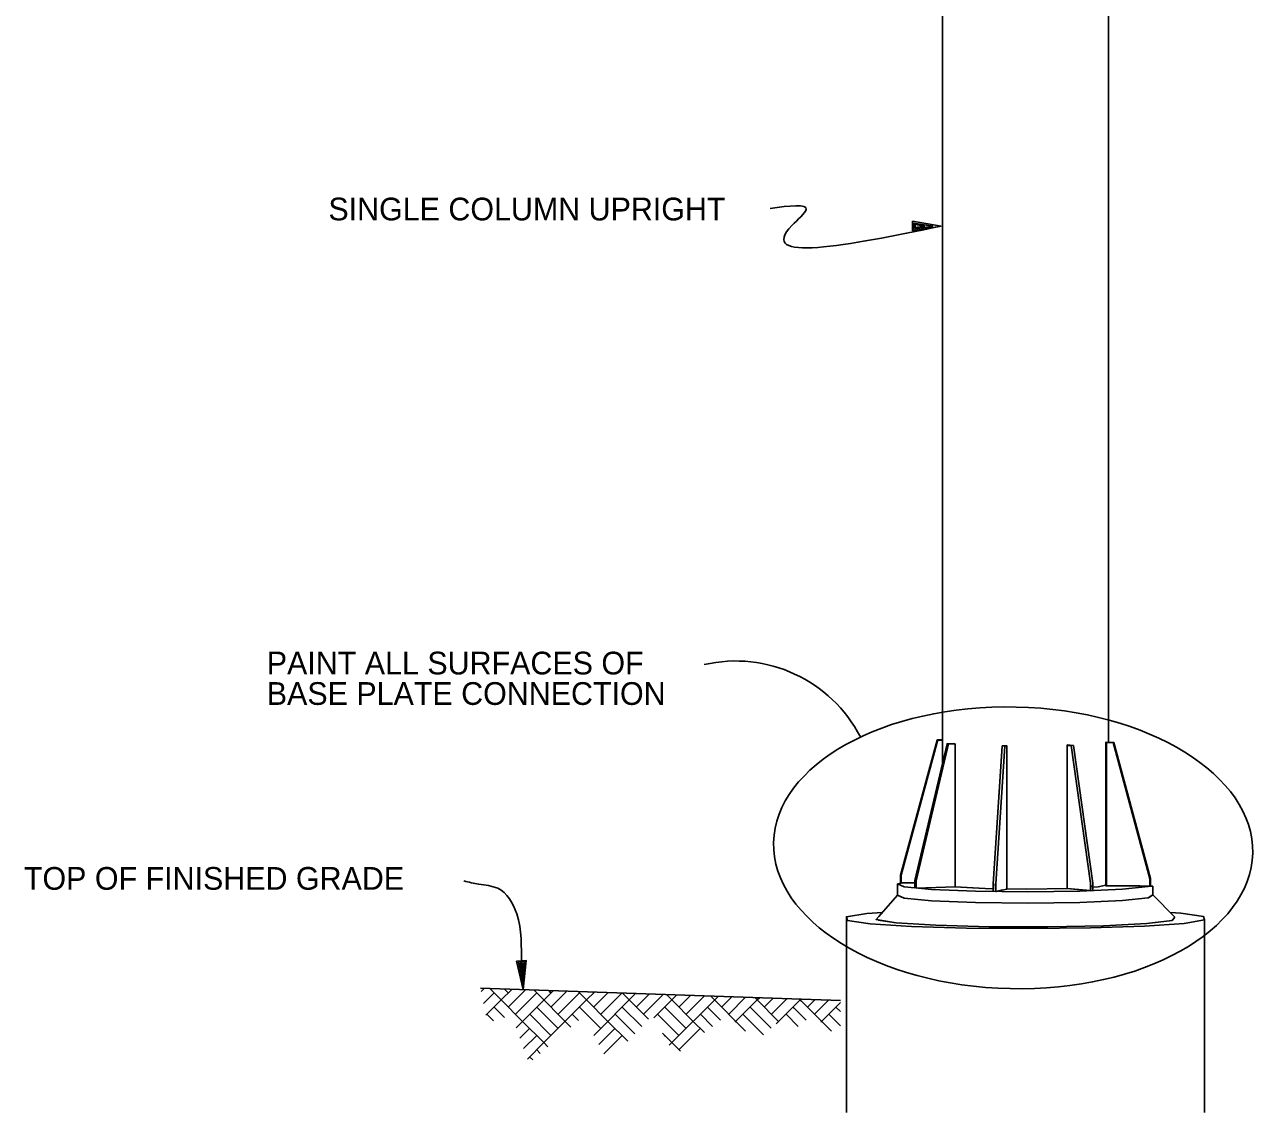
# Model space of a CAD drawing. Extents: x 10268852 to 10269008, y 2142584 to 2142686.
# Drawn here: x 10268878.83 to 10268915.61, y 2142620.73 to 2142653.26 of the extents above; entities that cross this region are included whole.
import ezdxf

# ---------------------------------------------------------------- set-up
doc = ezdxf.new("R2010")
doc.units = 0
doc.layers.add('SignDetail', color=7, linetype='Continuous')
doc.layers.add('TextLabel', color=7, linetype='Continuous')

msp = doc.modelspace()

# ---------------------------------------------------------------- linework, layer by layer
at = {"layer": 'SignDetail'}
for p, q in [((10268892.471, 2142624.439), (10268903.226, 2142624.073)), ((10268894.15, 2142624.302), (10268893.511, 2142623.664)), ((10268894.787, 2142623.666), (10268895.423, 2142624.302)), ((10268893.085, 2142624.09), (10268893.724, 2142623.451)), ((10268894.15, 2142623.877), (10268894.787, 2142623.24)), ((10268895, 2142623.453), (10268895.636, 2142624.09)), ((10268895.423, 2142623.877), (10268896.062, 2142623.238)), ((10268895.636, 2142624.09), (10268896.275, 2142623.451)), ((10268897.975, 2142623.877), (10268898.613, 2142623.238)), ((10268898.187, 2142624.09), (10268898.827, 2142623.451)), ((10268900.102, 2142623.453), (10268900.739, 2142624.09)), ((10268900.739, 2142624.09), (10268901.378, 2142623.451)), ((10268902.667, 2142623.453), (10268903.226, 2142624.012)), ((10268893.937, 2142623.664), (10268894.574, 2142623.027)), ((10268897.762, 2142623.664), (10268898.401, 2142623.025)), ((10268893.724, 2142623.451), (10268894.361, 2142622.814)), ((10268895, 2142623.453), (10268894.361, 2142622.814)), ((10268898.401, 2142622.603), (10268899.038, 2142623.24))]:
    msp.add_line(p, q, dxfattribs=at)
for points in [[(10268906.277, 2142665.654), (10268906.277, 2142631.914)], [(10268911.246, 2142663.913), (10268911.246, 2142631.798)], [(10268906.277, 2142647.077), (10268906.277, 2142631.161)], [(10268911.246, 2142647.077), (10268911.246, 2142631.797)], [(10268905.449, 2142627.589), (10268905.025, 2142627.595), (10268905.025, 2142627.82), (10268906.121, 2142631.864), (10268906.277, 2142631.862)], [(10268905.449, 2142627.589), (10268905.025, 2142627.595), (10268905.025, 2142627.82), (10268906.121, 2142631.864)], [(10268905.449, 2142627.593), (10268905.045, 2142627.599), (10268905.045, 2142627.825), (10268906.142, 2142631.869), (10268906.277, 2142631.867)], [(10268905.449, 2142627.593), (10268905.045, 2142627.599), (10268905.045, 2142627.825), (10268906.142, 2142631.869)], [(10268905.449, 2142627.435), (10268905.449, 2142627.66), (10268906.417, 2142631.753), (10268906.61, 2142631.759)], [(10268905.449, 2142627.66), (10268906.417, 2142631.753)], [(10268905.449, 2142627.66), (10268906.417, 2142631.753)], [(10268906.654, 2142631.755), (10268906.461, 2142631.748), (10268905.493, 2142627.656), (10268905.493, 2142627.43), (10268906.654, 2142627.47), (10268906.654, 2142631.755)], [(10268905.493, 2142627.656), (10268906.461, 2142631.748)], [(10268906.277, 2142631.862), (10268906.121, 2142631.864), (10268906.142, 2142631.869), (10268906.277, 2142631.867)], [(10268906.142, 2142631.869), (10268906.277, 2142631.867)], [(10268906.417, 2142631.753), (10268906.61, 2142631.759)], [(10268906.461, 2142631.748), (10268906.654, 2142631.755)], [(10268907.793, 2142627.56), (10268908.067, 2142631.695)], [(10268907.793, 2142627.56), (10268908.066, 2142631.681)], [(10268907.793, 2142627.335), (10268907.793, 2142627.56), (10268908.066, 2142631.681)], [(10268908.203, 2142627.408), (10268907.875, 2142627.334), (10268907.875, 2142627.559), (10268908.148, 2142631.68), (10268908.203, 2142631.692), (10268908.203, 2142627.408)], [(10268907.875, 2142627.559), (10268908.148, 2142631.68)], [(10268908.067, 2142631.695), (10268908.203, 2142631.692), (10268908.203, 2142627.408)], [(10268908.148, 2142631.68), (10268908.203, 2142631.692)], [(10268908.203, 2142631.693), (10268908.203, 2142627.408)], [(10268910.042, 2142631.704), (10268910.122, 2142631.697), (10268910.705, 2142627.583), (10268910.705, 2142627.358), (10268910.006, 2142627.423), (10268910.006, 2142631.717)], [(10268910.006, 2142631.717), (10268910.195, 2142631.699), (10268910.777, 2142627.585), (10268910.777, 2142627.36)], [(10268910.122, 2142631.697), (10268910.042, 2142631.704)], [(10268910.122, 2142631.697), (10268910.705, 2142627.583)], [(10268910.777, 2142627.585), (10268910.195, 2142631.7)], [(10268910.777, 2142627.585), (10268910.195, 2142631.699)], [(10268912.478, 2142627.715), (10268911.381, 2142631.79), (10268911.162, 2142631.793), (10268911.162, 2142627.508), (10268912.478, 2142627.49), (10268912.478, 2142627.715)], [(10268911.162, 2142631.793), (10268911.381, 2142631.79)], [(10268912.498, 2142627.495), (10268912.498, 2142627.72), (10268911.402, 2142631.795), (10268911.183, 2142631.798), (10268911.183, 2142627.513), (10268912.498, 2142627.495)], [(10268911.183, 2142631.798), (10268911.402, 2142631.795)], [(10268911.183, 2142631.798), (10268911.402, 2142631.795)], [(10268911.381, 2142631.79), (10268912.478, 2142627.715)], [(10268911.402, 2142631.795), (10268912.498, 2142627.72)], [(10268905.449, 2142627.444), (10268905.131, 2142627.474), (10268904.936, 2142627.563), (10268905.099, 2142627.593)], [(10268905.449, 2142627.444), (10268905.131, 2142627.474), (10268904.936, 2142627.563), (10268905.099, 2142627.593)], [(10268904.936, 2142627.563), (10268905.099, 2142627.593)], [(10268905.955, 2142627.058), (10268905.131, 2142627.136), (10268904.936, 2142627.225), (10268904.936, 2142627.563)], [(10268905.449, 2142627.593), (10268905.124, 2142627.598), (10268905.449, 2142627.593)], [(10268905.449, 2142627.593), (10268905.124, 2142627.598), (10268905.449, 2142627.593)], [(10268905.449, 2142627.435), (10268905.449, 2142627.66)], [(10268905.449, 2142627.435), (10268905.449, 2142627.66)], [(10268905.493, 2142627.656), (10268905.493, 2142627.43), (10268906.654, 2142627.47)], [(10268907.793, 2142627.56), (10268907.793, 2142627.335)], [(10268907.793, 2142627.335), (10268907.81, 2142627.56)], [(10268907.875, 2142627.559), (10268907.875, 2142627.334), (10268908.203, 2142627.408)], [(10268910.705, 2142627.583), (10268910.705, 2142627.358), (10268910.006, 2142627.423)], [(10268910.753, 2142627.51), (10268910.777, 2142627.36)], [(10268910.777, 2142627.36), (10268910.777, 2142627.585)], [(10268910.777, 2142627.467), (10268910.935, 2142627.477), (10268911.162, 2142627.528)], [(10268910.777, 2142627.467), (10268910.935, 2142627.477), (10268911.162, 2142627.528)], [(10268910.935, 2142627.477), (10268911.162, 2142627.528)], [(10268912.573, 2142627.489), (10268912.158, 2142627.495), (10268911.861, 2142627.499), (10268911.528, 2142627.503), (10268911.162, 2142627.511), (10268911.528, 2142627.503), (10268911.861, 2142627.499), (10268912.158, 2142627.495), (10268912.448, 2142627.49)], [(10268912.448, 2142627.49), (10268912.158, 2142627.495), (10268911.861, 2142627.499), (10268911.528, 2142627.503), (10268911.162, 2142627.511), (10268911.528, 2142627.503), (10268911.861, 2142627.499), (10268912.158, 2142627.495), (10268912.448, 2142627.49)], [(10268911.183, 2142627.513), (10268912.498, 2142627.495)], [(10268912.456, 2142627.495), (10268912.183, 2142627.499), (10268911.903, 2142627.503), (10268911.59, 2142627.507), (10268911.183, 2142627.512), (10268911.59, 2142627.507), (10268911.903, 2142627.503), (10268912.183, 2142627.499), (10268912.456, 2142627.495)], [(10268912.456, 2142627.495), (10268912.183, 2142627.499), (10268911.903, 2142627.503), (10268911.59, 2142627.507), (10268911.183, 2142627.512), (10268911.59, 2142627.507), (10268911.903, 2142627.503), (10268912.183, 2142627.499), (10268912.456, 2142627.495)], [(10268912.478, 2142627.49), (10268912.478, 2142627.715)], [(10268912.498, 2142627.72), (10268912.498, 2142627.495)], [(10268906.076, 2142626.325), (10268904.89, 2142626.398), (10268904.294, 2142626.492), (10268904.377, 2142626.591), (10268904.936, 2142627.225), (10268905.131, 2142627.136), (10268905.955, 2142627.058)], [(10268905.131, 2142627.136), (10268904.936, 2142627.225)], [(10268905.131, 2142627.136), (10268904.936, 2142627.225)], [(10268904.936, 2142627.225), (10268905.131, 2142627.136), (10268905.955, 2142627.058), (10268907.263, 2142627.007), (10268908.83, 2142626.989)], [(10268905.493, 2142627.431), (10268906.654, 2142627.47)], [(10268905.955, 2142627.397), (10268905.565, 2142627.433)], [(10268905.565, 2142627.433), (10268905.955, 2142627.397), (10268907.263, 2142627.345), (10268908.83, 2142627.328)], [(10268905.955, 2142627.397), (10268907.263, 2142627.345), (10268908.83, 2142627.328), (10268910.386, 2142627.348)], [(10268906.654, 2142627.471), (10268907.347, 2142627.433)], [(10268906.654, 2142627.471), (10268907.558, 2142627.422)], [(10268906.654, 2142627.471), (10268907.347, 2142627.433)], [(10268906.654, 2142627.471), (10268907.558, 2142627.422), (10268907.793, 2142627.418)], [(10268906.654, 2142627.471), (10268907.558, 2142627.422)], [(10268907.558, 2142627.422), (10268907.793, 2142627.418)], [(10268907.558, 2142627.422), (10268907.793, 2142627.418)], [(10268907.876, 2142627.334), (10268908.203, 2142627.408)], [(10268908.078, 2142627.38), (10268907.876, 2142627.338), (10268908.078, 2142627.38)], [(10268908.078, 2142627.38), (10268907.876, 2142627.338), (10268907.895, 2142627.338), (10268907.876, 2142627.338), (10268908.078, 2142627.38)], [(10268907.89, 2142627.338), (10268907.895, 2142627.338)], [(10268908.203, 2142627.413), (10268908.806, 2142627.404), (10268910.006, 2142627.424)], [(10268908.203, 2142627.413), (10268908.806, 2142627.404), (10268910.006, 2142627.424)], [(10268908.203, 2142627.413), (10268908.806, 2142627.404)], [(10268908.806, 2142627.404), (10268910.006, 2142627.424)], [(10268908.83, 2142627.328), (10268910.386, 2142627.348), (10268911.661, 2142627.402)], [(10268910.006, 2142627.423), (10268910.124, 2142627.412), (10268910.587, 2142627.369), (10268910.124, 2142627.412), (10268910.006, 2142627.423)], [(10268910.006, 2142627.423), (10268910.124, 2142627.412), (10268910.587, 2142627.369), (10268910.124, 2142627.412), (10268910.006, 2142627.423)], [(10268910.705, 2142627.358), (10268910.006, 2142627.423)], [(10268910.386, 2142627.348), (10268911.661, 2142627.402)], [(10268910.704, 2142627.362), (10268910.587, 2142627.368), (10268910.704, 2142627.362)], [(10268910.704, 2142627.362), (10268910.587, 2142627.368), (10268910.704, 2142627.362)], [(10268910.777, 2142627.467), (10268910.935, 2142627.477), (10268911.069, 2142627.507)], [(10268910.777, 2142627.467), (10268910.935, 2142627.477), (10268911.069, 2142627.507)], [(10268910.777, 2142627.467), (10268910.935, 2142627.477)], [(10268911.162, 2142627.508), (10268912.478, 2142627.49)], [(10268911.661, 2142627.402), (10268912.434, 2142627.481)], [(10268911.661, 2142627.402), (10268912.434, 2142627.481)], [(10268911.661, 2142627.064), (10268912.434, 2142627.143), (10268912.573, 2142627.233)], [(10268911.661, 2142627.064), (10268912.434, 2142627.143), (10268912.573, 2142627.233), (10268913.227, 2142626.57)], [(10268911.661, 2142627.064), (10268912.434, 2142627.143)], [(10268911.661, 2142627.064), (10268912.434, 2142627.143)], [(10268911.661, 2142627.064), (10268912.434, 2142627.143)], [(10268912.434, 2142627.143), (10268912.573, 2142627.233), (10268912.573, 2142627.489)], [(10268912.435, 2142627.143), (10268912.573, 2142627.233)], [(10268912.435, 2142627.143), (10268912.573, 2142627.233)], [(10268905.131, 2142627.136), (10268905.955, 2142627.058)], [(10268905.131, 2142627.136), (10268905.955, 2142627.058)], [(10268905.955, 2142627.058), (10268907.263, 2142627.007), (10268908.83, 2142626.989)], [(10268905.955, 2142627.058), (10268907.263, 2142627.007)], [(10268905.955, 2142627.058), (10268907.263, 2142627.007), (10268908.83, 2142626.989), (10268910.386, 2142627.01)], [(10268905.955, 2142627.058), (10268907.263, 2142627.007)], [(10268907.263, 2142627.007), (10268908.831, 2142626.99)], [(10268907.263, 2142627.007), (10268908.831, 2142626.99)], [(10268908.83, 2142626.989), (10268910.386, 2142627.01), (10268911.661, 2142627.064)], [(10268908.83, 2142626.989), (10268910.386, 2142627.01)], [(10268908.83, 2142626.989), (10268910.386, 2142627.01)], [(10268908.83, 2142626.989), (10268910.386, 2142627.01)], [(10268910.386, 2142627.01), (10268911.661, 2142627.064)], [(10268910.386, 2142627.01), (10268911.661, 2142627.064)], [(10268910.386, 2142627.01), (10268911.661, 2142627.064)], [(10268910.386, 2142627.01), (10268911.661, 2142627.064)], [(10268908.859, 2142626.224), (10268906.999, 2142626.24), (10268905.352, 2142626.292), (10268904.116, 2142626.372), (10268903.441, 2142626.471), (10268903.407, 2142626.577), (10268904.018, 2142626.678), (10268904.482, 2142626.711)], [(10268903.407, 2142620.727), (10268903.407, 2142626.578), (10268904.018, 2142626.679), (10268904.482, 2142626.711)], [(10268903.407, 2142626.577), (10268904.019, 2142626.678)], [(10268903.407, 2142626.577), (10268903.441, 2142626.471), (10268904.116, 2142626.372), (10268905.352, 2142626.292), (10268906.999, 2142626.24), (10268908.859, 2142626.224)], [(10268904.018, 2142626.678), (10268904.482, 2142626.711)], [(10268904.89, 2142626.398), (10268904.361, 2142626.481)], [(10268904.89, 2142626.398), (10268904.361, 2142626.481)], [(10268908.859, 2142626.224), (10268910.707, 2142626.244), (10268912.32, 2142626.299), (10268913.504, 2142626.381), (10268914.116, 2142626.482), (10268914.083, 2142626.588), (10268913.407, 2142626.688), (10268913.091, 2142626.708)], [(10268911.09, 2142626.311), (10268912.394, 2142626.378), (10268913.146, 2142626.468), (10268913.229, 2142626.568)], [(10268911.643, 2142626.339), (10268912.394, 2142626.378), (10268913.146, 2142626.468)], [(10268911.643, 2142626.339), (10268912.394, 2142626.378), (10268913.146, 2142626.468)], [(10268912.32, 2142626.299), (10268913.504, 2142626.381), (10268914.116, 2142626.482), (10268914.083, 2142626.588), (10268913.407, 2142626.688), (10268913.091, 2142626.708)], [(10268914.116, 2142626.482), (10268914.083, 2142626.588), (10268913.407, 2142626.688), (10268913.09, 2142626.708)], [(10268913.146, 2142626.468), (10268913.168, 2142626.495)], [(10268913.146, 2142626.468), (10268913.168, 2142626.495)], [(10268914.116, 2142620.727), (10268914.116, 2142626.482)], [(10268904.89, 2142626.398), (10268905.003, 2142626.391)], [(10268904.89, 2142626.398), (10268905.003, 2142626.391)], [(10268906.076, 2142626.325), (10268907.671, 2142626.282)], [(10268907.671, 2142626.282), (10268909.431, 2142626.277)], [(10268907.845, 2142626.282), (10268909.431, 2142626.278)], [(10268907.845, 2142626.282), (10268909.431, 2142626.278)], [(10268908.859, 2142626.224), (10268910.707, 2142626.244), (10268912.32, 2142626.299)], [(10268909.431, 2142626.277), (10268911.09, 2142626.311)], [(10268909.432, 2142626.278), (10268909.71, 2142626.283)], [(10268909.432, 2142626.278), (10268909.71, 2142626.283)], [(10268892.489, 2142624.345), (10268892.578, 2142624.435)], [(10268892.559, 2142623.989), (10268892.872, 2142624.302)], [(10268892.746, 2142624.429), (10268893.085, 2142624.09)], [(10268893.402, 2142624.406), (10268893.085, 2142624.09)], [(10268893.187, 2142624.414), (10268893.298, 2142624.302)], [(10268893.814, 2142624.393), (10268893.298, 2142623.877)], [(10268893.528, 2142623.255), (10268894.638, 2142624.365)], [(10268895.171, 2142623.281), (10268894.068, 2142624.384)], [(10268894.505, 2142624.369), (10268894.574, 2142624.3)], [(10268894.574, 2142623.879), (10268895.046, 2142624.351)], [(10268895.387, 2142624.339), (10268895.636, 2142624.09)], [(10268895.87, 2142624.323), (10268895.636, 2142624.09)], [(10268895.828, 2142624.324), (10268895.849, 2142624.302)], [(10268896.282, 2142624.309), (10268895.849, 2142623.877)], [(10268895.851, 2142623.026), (10268897.105, 2142624.281)], [(10268896.693, 2142624.295), (10268896.062, 2142623.664)], [(10268897.492, 2142623.512), (10268896.71, 2142624.294)], [(10268897.125, 2142623.879), (10268897.513, 2142624.267)], [(10268897.338, 2142623.666), (10268897.925, 2142624.253)], [(10268898.028, 2142624.249), (10268898.187, 2142624.09)], [(10268898.337, 2142624.239), (10268898.187, 2142624.09)], [(10268898.749, 2142624.225), (10268898.401, 2142623.877)], [(10268899.161, 2142624.211), (10268898.613, 2142623.664)], [(10268900.393, 2142623.162), (10268899.351, 2142624.205)], [(10268892.629, 2142623.633), (10268893.085, 2142624.09)], [(10268892.872, 2142623.877), (10268893.181, 2142623.567)], [(10268896.701, 2142623.877), (10268897.285, 2142623.293)], [(10268897.651, 2142623.553), (10268898.187, 2142624.09)], [(10268898.111, 2142622.735), (10268899.573, 2142624.197)], [(10268899.253, 2142623.877), (10268899.642, 2142623.487)], [(10268899.676, 2142623.879), (10268899.981, 2142624.183)], [(10268899.889, 2142623.666), (10268900.392, 2142624.169)], [(10268900.526, 2142623.877), (10268901.155, 2142623.247)], [(10268900.669, 2142624.16), (10268900.739, 2142624.09)], [(10268900.804, 2142624.155), (10268900.739, 2142624.09)], [(10268901.217, 2142624.141), (10268900.952, 2142623.877)], [(10268901.628, 2142624.127), (10268901.165, 2142623.664)], [(10268901.308, 2142623.381), (10268902.04, 2142624.113)], [(10268901.804, 2142623.877), (10268901.838, 2142623.843)], [(10268901.817, 2142623.877), (10268902.206, 2142623.487)], [(10268902.066, 2142624.041), (10268901.991, 2142624.115)], [(10268902.958, 2142623.162), (10268902.005, 2142624.115)], [(10268902.241, 2142623.879), (10268902.461, 2142624.099)], [(10268902.454, 2142623.666), (10268902.873, 2142624.085)], [(10268903.091, 2142623.877), (10268903.226, 2142623.741)], [(10268892.659, 2142623.664), (10268892.858, 2142623.465)], [(10268895.21, 2142623.664), (10268895.397, 2142623.477)], [(10268896.488, 2142623.664), (10268897.078, 2142623.074)], [(10268899.04, 2142623.664), (10268899.403, 2142623.3)], [(10268900.313, 2142623.664), (10268900.927, 2142623.049)], [(10268901.591, 2142623.664), (10268901.61, 2142623.644)], [(10268901.604, 2142623.664), (10268901.967, 2142623.3)], [(10268902.878, 2142623.664), (10268903.226, 2142623.315)], [(10268893.641, 2142622.946), (10268893.935, 2142623.24)], [(10268896.002, 2142622.755), (10268896.486, 2142623.24)], [(10268896.275, 2142623.451), (10268896.871, 2142622.855)], [(10268898.827, 2142623.451), (10268899.164, 2142623.114)], [(10268900.102, 2142623.453), (10268900.076, 2142623.426)], [(10268900.315, 2142623.24), (10268900.308, 2142623.233)], [(10268901.378, 2142623.451), (10268901.382, 2142623.446)], [(10268902.667, 2142623.453), (10268902.64, 2142623.426)], [(10268902.879, 2142623.24), (10268902.872, 2142623.233)], [(10268893.756, 2142622.635), (10268894.148, 2142623.027)], [(10268893.87, 2142622.324), (10268894.361, 2142622.814)], [(10268894.361, 2142622.814), (10268894.484, 2142622.691)], [(10268896.154, 2142622.482), (10268896.699, 2142623.027)], [(10268898.448, 2142622.556), (10268897.909, 2142623.095)], [(10268897.977, 2142623.027), (10268897.958, 2142623.008)], [(10268893.935, 2142622.388), (10268894.026, 2142622.296)], [(10268894.148, 2142622.601), (10268894.255, 2142622.494)]]:
    msp.add_lwpolyline(points, dxfattribs=at)
at = {"layer": 'TextLabel'}
for points in [[(10268906.242, 2142647.231), (10268905.384, 2142647.093), (10268905.385, 2142647.381)], [(10268905.988, 2142647.233), (10268905.411, 2142647.147), (10268905.412, 2142647.326)], [(10268905.755, 2142647.235), (10268905.46, 2142647.188), (10268905.46, 2142647.284)], [(10268893.745, 2142624.401), (10268893.835, 2142625.267), (10268893.547, 2142625.248)], [(10268893.729, 2142624.655), (10268893.782, 2142625.236), (10268893.604, 2142625.224)], [(10268893.714, 2142624.888), (10268893.744, 2142625.185), (10268893.648, 2142625.179)]]:
    msp.add_lwpolyline(points, close=True, dxfattribs=at)
msp.add_arc((10268900.093, 2142630.03), 4.198, 27.3071, 102.9353, dxfattribs=at)
msp.add_ellipse((10268908.392, 2142628.64), major_axis=(7.162, -0.159), ratio=0.588001, dxfattribs=at)
for points in [[(10268906.242, 2142647.231), (10268901.783, 2142647.259), (10268902.202, 2142647.73), (10268901.132, 2142647.763)], [(10268891.971, 2142627.652), (10268892.416, 2142627.552), (10268892.98, 2142627.43), (10268893.548, 2142626.668), (10268893.695, 2142625.191), (10268893.745, 2142624.401)]]:
    msp.add_spline(points, degree=3, dxfattribs=at)

# ---------------------------------------------------------------- texts
for s, p in [('SINGLE COLUMN UPRIGHT', (10268887.918, 2142647.405)), ('PAINT ALL SURFACES OF ', (10268886.076, 2142633.826)), ('BASE PLATE CONNECTION', (10268886.076, 2142632.915)), ('TOP OF FINISHED GRADE', (10268878.814, 2142627.386))]:
    msp.add_text(s, height=0.68, dxfattribs=at).set_placement(p)

doc.saveas('drawing.dxf')
